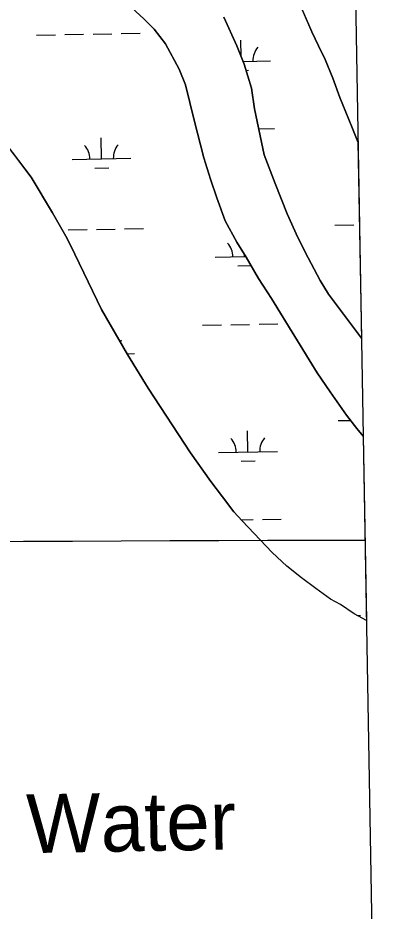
# Model space of a CAD drawing. Extents: x 3892998 to 3931244, y 278583 to 304547.
# Drawn here: x 3928340 to 3928977, y 296055 to 297577 of the extents above; entities that cross this region are included whole.
import ezdxf

# ---------------------------------------------------------------- set-up
doc = ezdxf.new("R2010")
doc.units = 0
for name, color, linetype in [('V-GRID-FRAM', 7, 'Continuous'), ('V-GRID-MAJR', 7, 'Continuous'), ('V-RIVR-IDEN', 7, 'Continuous'), ('V-TOPO-SHOR', 7, 'Continuous'), ('V-WETL-SWMP', 7, 'Continuous')]:
    doc.layers.add(name, color=color, linetype=linetype)

msp = doc.modelspace()

# ---------------------------------------------------------------- linework, layer by layer
at = {"layer": 'V-GRID-FRAM'}
msp.add_lwpolyline([(3896958.365, 302195.156), (3928823.6380000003, 302746.745), (3929146.2630000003, 284567.099), (3897265.125, 284015.23600000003), (3896958.365, 302195.156)], dxfattribs=at)
at = {"layer": 'V-GRID-MAJR'}
msp.add_spline([(3897060.6180000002, 296135.19), (3902372.4110000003, 296225.205), (3907684.191, 296315.993), (3912995.9590000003, 296407.553), (3918307.7120000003, 296499.886), (3923619.453, 296592.991), (3928931.179, 296686.869), (3928931.18, 296686.869)], degree=3, dxfattribs=at)
at = {"layer": 'V-TOPO-SHOR'}
for points in [[(3928382.8200000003, 297774.214), (3928320.5360000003, 297864.748), (3928250.208, 297965.688), (3928213.049, 298012.855), (3928186.392, 298032.325), (3928153.903, 298048.107), (3928111.5360000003, 298064.444), (3928068.171, 298079.212), (3928050.403, 298083.468), (3928040.468, 298081.795), (3928034.015, 298078.75800000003), (3928022.863, 298066.263), (3928019.1070000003, 298056.14), (3928012.437, 298017.686), (3927998.775, 297927.386), (3927992.33, 297818.719), (3927995.383, 297799.818), (3928000.11, 297784.069), (3928024.477, 297749.015), (3928148.545, 297587.107), (3928363.227, 297305.257)], [(3928919.1421775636, 297365.1653343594), (3928908.497, 297390.935), (3928888.037, 297440.988), (3928876.37, 297473.979), (3928863.531, 297505.58400000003), (3928851.736, 297529.12200000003), (3928840.7260000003, 297553.061), (3928812.075, 297619.002)], [(3928928.0296127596, 296864.3658745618), (3928917.301, 296876.93), (3928899.6, 296900.03500000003), (3928871.927, 296939.412), (3928849.821, 296972.137), (3928811.544, 297033.886), (3928771.864, 297098.777), (3928749.944, 297132.684), (3928728.799, 297168.764), (3928713.046, 297194.446), (3928692.879, 297231.121), (3928679, 297269.816), (3928668.125, 297301.837), (3928656.625, 297338.184), (3928640.188, 297402.463), (3928625.756, 297462.422), (3928615.116, 297489.126), (3928591.356, 297532.472), (3928572.063, 297557.538), (3928554.598, 297575.132), (3928527.431, 297599.939)], [(3928690.821, 297578.042), (3928713.044, 297528.984), (3928725.485, 297497.969), (3928737.806, 297456.715), (3928742.875, 297421.43), (3928759.804, 297343.35000000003), (3928778.481, 297294.464), (3928798.759, 297242.635), (3928816.781, 297202.406), (3928834.369, 297167.688), (3928854.739, 297129.446), (3928869.093, 297105.927), (3928925.069683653, 297031.1553774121)], [(3928363.227, 297305.257), (3928399.333, 297244.278), (3928424.2800000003, 297200.547), (3928437.477, 297174.06), (3928482.693, 297080.063), (3928526.794, 297003.189), (3928562.083, 296946.14400000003), (3928634.007, 296836.003), (3928668.645, 296786.828), (3928688.535, 296760.786), (3928707.829, 296735.52400000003), (3928721.932, 296719.676), (3928773.347, 296665.705), (3928798.335, 296642.458)]]:
    msp.add_lwpolyline(points, dxfattribs=at)
at = {"layer": 'V-WETL-SWMP'}
for p, q in [((3928812.075, 297619.002), (3928840.727, 297553.05999999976)), ((3928527.431, 297599.939), (3928554.599, 297575.13099999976)), ((3928363.227, 297305.257), (3928148.545, 297587.106)), ((3928713.044, 297528.98499999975), (3928690.8200000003, 297578.042)), ((3928554.599, 297575.13099999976), (3928572.063, 297557.537)), ((3928372.2981212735, 297547.19923549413), (3928404.2933280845, 297547.7530776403)), ((3928420.2909314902, 297548.029998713), (3928452.286138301, 297548.5838408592)), ((3928468.2837417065, 297548.86076193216), (3928500.2789485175, 297549.4146040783)), ((3928516.276551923, 297549.69152515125), (3928548.271758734, 297550.2453672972)), ((3928572.063, 297557.537), (3928591.355, 297532.473)), ((3928840.727, 297553.05999999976), (3928851.736, 297529.12199999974)), ((3928591.355, 297532.473), (3928615.117, 297489.12699999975)), ((3928720.294332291, 297510.9095795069), (3928719.817245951, 297538.4706386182)), ((3928725.485, 297497.969), (3928713.044, 297528.98499999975)), ((3928851.736, 297529.12199999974), (3928863.5300000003, 297505.583)), ((3928723.6548401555, 297502.5316748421), (3928770.4328290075, 297503.3414093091)), ((3928863.5300000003, 297505.583), (3928876.369, 297473.979)), ((3928615.117, 297489.12699999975), (3928625.756, 297462.422)), ((3928737.805, 297456.71399999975), (3928725.485, 297497.969)), ((3928728.7051963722, 297487.18578560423), (3928732.7055939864, 297487.2550331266)), ((3928876.369, 297473.979), (3928888.0360000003, 297440.9879999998)), ((3928625.756, 297462.422), (3928640.1890000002, 297402.463)), ((3928742.875, 297421.429), (3928737.805, 297456.71399999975)), ((3928888.0360000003, 297440.9879999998), (3928908.4960000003, 297390.934)), ((3928759.804, 297343.34899999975), (3928742.875, 297421.429)), ((3928640.1890000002, 297402.463), (3928656.625, 297338.18499999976)), ((3928750.2221888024, 297387.54226707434), (3928777.021988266, 297388.00617588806)), ((3928908.4960000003, 297390.934), (3928919.14219549, 297365.1643242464)), ((3928482.805775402, 297336.4762905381), (3928482.1827029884, 297372.47089820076)), ((3928919.14219549, 297365.1643242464), (3928925.0697079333, 297031.1540092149)), ((3928432.8132647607, 297335.610912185), (3928532.798286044, 297337.34166889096)), ((3928656.625, 297338.18499999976), (3928668.1240000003, 297301.837)), ((3928778.4820000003, 297294.463), (3928759.804, 297343.34899999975)), ((3928471.0746459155, 297320.83991109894), (3928495.0710510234, 297321.25529270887)), ((3928399.332, 297244.278), (3928363.227, 297305.257)), ((3928668.1240000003, 297301.837), (3928678.9990000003, 297269.816)), ((3928798.758, 297242.6349999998), (3928778.4820000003, 297294.463)), ((3928678.9990000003, 297269.816), (3928692.879, 297231.12199999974)), ((3928424.279, 297200.547), (3928399.332, 297244.278)), ((3928816.781, 297202.406), (3928798.758, 297242.6349999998)), ((3928692.879, 297231.12199999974), (3928713.046, 297194.4449999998)), ((3928426.048726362, 297215.4048291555), (3928458.043933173, 297215.9586713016)), ((3928474.0415365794, 297216.2355923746), (3928506.0367433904, 297216.7894345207)), ((3928522.034346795, 297217.0663555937), (3928554.0295536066, 297217.6201977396)), ((3928879.8887367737, 297223.26087230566), (3928911.8839435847, 297223.8147144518)), ((3928437.4760000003, 297174.059), (3928424.279, 297200.547)), ((3928834.369, 297167.688), (3928816.781, 297202.406)), ((3928713.046, 297194.4449999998), (3928728.798, 297168.764)), ((3928482.6920000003, 297080.06199999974), (3928437.4760000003, 297174.059)), ((3928676.2056025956, 297168.98548304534), (3928728.1110393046, 297169.88397445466)), ((3928726.1981132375, 297169.85086139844), (3928726.1419703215, 297173.0942119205)), ((3928728.798, 297168.764), (3928749.9450000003, 297132.685)), ((3928854.739, 297129.44699999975), (3928834.369, 297167.688)), ((3928714.466983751, 297154.21448195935), (3928737.0963178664, 297154.60619935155)), ((3928749.9450000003, 297132.685), (3928771.864, 297098.778)), ((3928869.092, 297105.927), (3928854.739, 297129.44699999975)), ((3928925.0697079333, 297031.1540092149), (3928869.092, 297105.927)), ((3928771.864, 297098.778), (3928811.544, 297033.887)), ((3928526.795, 297003.19), (3928482.6920000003, 297080.06199999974)), ((3928654.7989558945, 297053.16563774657), (3928686.7941627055, 297053.7194798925)), ((3928702.7917661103, 297053.99640096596), (3928734.786972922, 297054.5502431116)), ((3928750.7845763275, 297054.8271641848), (3928782.7797831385, 297055.3810063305)), ((3928811.544, 297033.887), (3928849.821, 296972.13699999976)), ((3928526.0434818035, 297004.49990424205), (3928538.5560809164, 297004.7164993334)), ((3928562.083, 296946.145), (3928526.795, 297003.19)), ((3928849.821, 296972.13699999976), (3928871.9280000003, 296939.413)), ((3928634.008, 296836.002), (3928562.083, 296946.145)), ((3928871.9280000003, 296939.413), (3928899.599, 296900.03500000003)), ((3928899.599, 296900.03500000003), (3928917.301, 296876.929)), ((3928885.6465316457, 296890.6357027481), (3928906.523143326, 296890.9970802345)), ((3928731.95590811, 296837.22569184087), (3928731.3328356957, 296873.22029950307)), ((3928917.301, 296876.929), (3928928.029624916, 296864.3651895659)), ((3928928.029624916, 296864.3651895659), (3928933.6061051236, 296550.13524430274)), ((3928668.645, 296786.829), (3928634.008, 296836.002)), ((3928681.9633974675, 296836.36031348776), (3928781.9484187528, 296838.09107019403)), ((3928720.2247786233, 296821.5893124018), (3928744.221183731, 296822.00469401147)), ((3928688.5360000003, 296760.78500000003), (3928668.645, 296786.829)), ((3928707.829, 296735.52400000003), (3928688.5360000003, 296760.78500000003)), ((3928721.931, 296719.677), (3928707.829, 296735.52400000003)), ((3928720.243200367, 296721.5736501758), (3928740.5447677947, 296721.92507355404)), ((3928773.346, 296665.706), (3928721.931, 296719.677)), ((3928756.5423711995, 296722.20199462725), (3928788.5375780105, 296722.7558367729)), ((3928798.335, 296642.458), (3928773.346, 296665.706)), ((3928823.1, 296622.9489999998), (3928798.335, 296642.458)), ((3928847.265, 296604.618), (3928823.1, 296622.9489999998)), ((3928872.412, 296586.688), (3928847.265, 296604.618)), ((3928889.6180000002, 296577.167), (3928872.412, 296586.688)), ((3928912.776, 296561.782), (3928889.6180000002, 296577.167)), ((3928933.6061051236, 296550.13524430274), (3928912.776, 296561.782)), ((3928918.676897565, 296558.4826257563), (3928923.3995333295, 296558.56437533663))]:
    msp.add_line(p, q, dxfattribs=at)
for centre, radius, start, end in [((3928775.6667620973, 297503.90688384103), 35.246287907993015, 140.21987699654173, 181.76353532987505), ((3928427.5628962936, 297335.9949017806), 35.24628790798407, 0.21988000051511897, 41.76353833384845), ((3928538.0322191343, 297337.9071434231), 35.246287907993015, 140.21987699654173, 181.76353532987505), ((3928670.95523413, 297169.36947264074), 35.24628790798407, 0.21988000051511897, 41.76353833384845), ((3928543.7900140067, 297005.2819738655), 35.246287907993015, 140.2198769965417, 146.444532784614), ((3928676.7130290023, 296836.74430308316), 35.24628790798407, 0.21988000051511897, 41.76353833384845), ((3928787.182351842, 296838.6565447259), 35.246287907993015, 140.21987699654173, 181.76353532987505)]:
    msp.add_arc(centre, radius, start, end, dxfattribs=at)

# ---------------------------------------------------------------- texts
at = {"layer": 'V-RIVR-IDEN'}
msp.add_text('Water', height=99.99980199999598, rotation=1.0479916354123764, dxfattribs=at).set_placement((3928355.735248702, 296153.84366701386))

doc.saveas('drawing.dxf')
